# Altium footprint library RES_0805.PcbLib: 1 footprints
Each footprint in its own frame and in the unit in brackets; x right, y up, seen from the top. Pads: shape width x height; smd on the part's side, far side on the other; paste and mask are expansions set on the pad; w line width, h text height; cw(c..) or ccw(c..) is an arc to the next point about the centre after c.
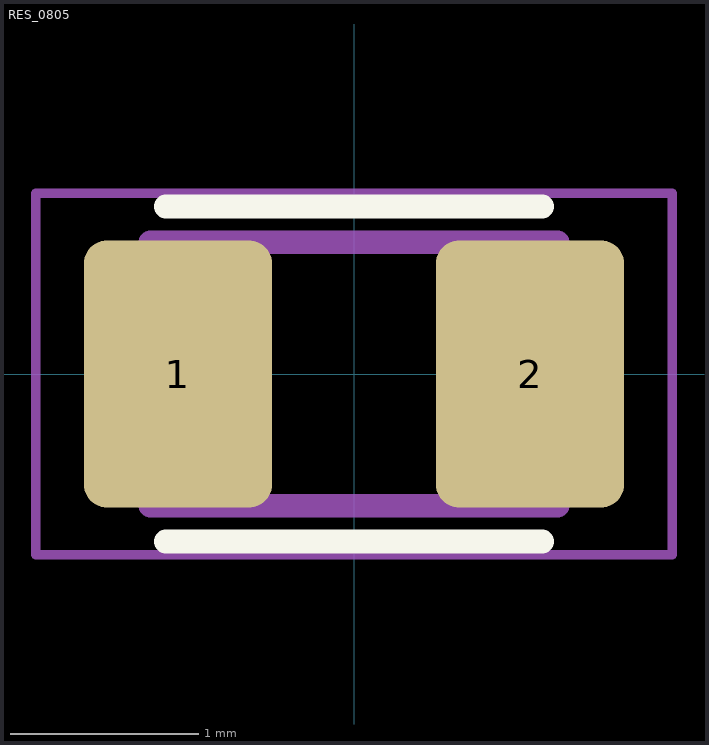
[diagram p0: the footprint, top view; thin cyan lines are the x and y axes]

## RES_0805 [mm]
pads (2):
  rrect25% 1x1.42 smd: 1(-0.935,0) 2(0.935,0)
Top Overlay:
  lines w0.127: -1,-0.89 1,-0.89 ; -1,0.89 1,0.89
Mechanical 13:
  lines w0.127: -1.08,-0.7 -1.08,0.7 1.08,0.7 1.08,-0.7 -1.08,-0.7
Mechanical 15:
  lines w0.05: -1.69,-0.96 -1.69,0.96 1.69,0.96 1.69,-0.96 -1.69,-0.96
3D body "RES_0805.STEP": height 1.1, standoff 0, extent -1,-0.625 1,0.625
